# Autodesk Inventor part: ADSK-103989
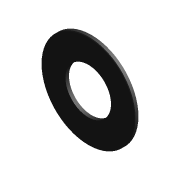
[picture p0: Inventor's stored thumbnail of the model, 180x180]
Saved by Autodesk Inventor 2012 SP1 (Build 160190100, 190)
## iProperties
Shininess: 0.0
Created: 2000-11
Part Number: ADSK-103989
Document SubType Name: Modeling
Stock Number: ADSK-103989
Density: 1 g/cm^3
Material: Default
Density: 0.0
Volumn: 0.0
Area: 0.0
PropertySet Name: Model Information
Control State: 0
Master: False
Checked Out: False
Author: gao
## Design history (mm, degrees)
node "Extrusion1" dims "d1" = 11.6586, "d2" = 0
  sketch "Sketch1"
    geometry: C1 r 157.099 at (-0.585, -0.634)
    constraints: 1 centre point
    dimensions: "d0" = 314.198 diameter of C1
node "Chamfer1" dims "d12" = 3.175, "d13" = 15 deg, "d23" = 3.175
node "Chamfer2" dims "d14" = 3.175, "d15" = 15 deg, "d24" = 3.175
node "Hole2" dims "d16" = 152.4, "d17" = 9.525, "d18" = 6.35, "d19" = 60 deg, "d20" = 19.05, "d21" = 118 deg
  sketch "Sketch4"
    geometry: C1 r 153.924 at (0, 0) reference; 1 further point
    constraints: 1 coincident
workplane "Work Plane1"
body "Solid1"
other parameters: "d22" = -5.8293 (= -0.5 x d1)
